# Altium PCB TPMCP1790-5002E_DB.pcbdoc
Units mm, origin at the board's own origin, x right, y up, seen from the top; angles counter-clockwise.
Board outline 20.84 x 19.35 mm, 2 copper layers (Top Layer, Bottom Layer), stack 0 mm thick; 1 components, 0 nets, 4 pads, 0 vias.
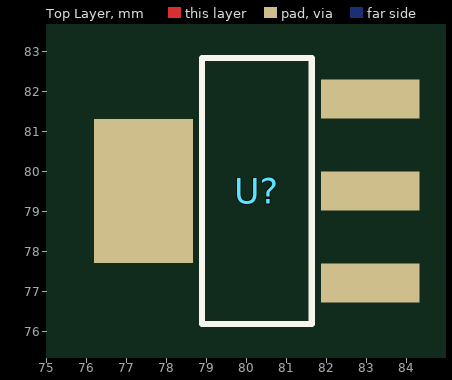
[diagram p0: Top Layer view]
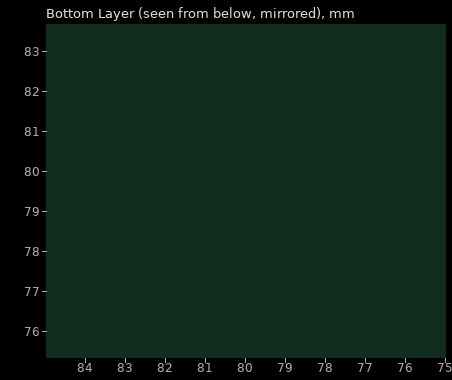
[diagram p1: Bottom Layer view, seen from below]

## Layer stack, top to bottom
Top Layer: signal copper (thickness not stored)
Bottom Layer: signal copper (thickness not stored)

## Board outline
90.69,69.85 69.85,69.85 69.85,89.202 90.69,89.202

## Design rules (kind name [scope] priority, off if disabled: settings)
PasteMaskExpansion "Paste Mask Expansion" [All] p1: expansion=0
SolderMaskExpansion "Solder Mask Expansion" [IsVia] p1: expansion=-25.4 istentingtop=TRUE
SolderMaskExpansion "Solder Mask Expansion" [All] p2: expansion=0.051 istentingtop=FALSE

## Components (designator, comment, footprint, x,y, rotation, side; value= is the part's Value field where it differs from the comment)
U? "TPMCP1790-5002E/DB" SOT-223-4_L6.5-W3.5-P2.30-LS7.0-BR 80.27,79.526 r0 top

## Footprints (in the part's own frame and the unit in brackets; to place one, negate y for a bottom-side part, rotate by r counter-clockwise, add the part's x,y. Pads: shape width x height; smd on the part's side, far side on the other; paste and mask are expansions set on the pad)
SOT-223-4_L6.5-W3.5-P2.30-LS7.0-BR [mm]
  rect 2.47x0.98 smd: 1(2.835,-2.3) 2(2.835,0) 3(2.835,2.3)
  rect 2.47x3.6 smd: 4(-2.835,0)
  silkscreen extent -1.37,-3.33 1.37,3.33

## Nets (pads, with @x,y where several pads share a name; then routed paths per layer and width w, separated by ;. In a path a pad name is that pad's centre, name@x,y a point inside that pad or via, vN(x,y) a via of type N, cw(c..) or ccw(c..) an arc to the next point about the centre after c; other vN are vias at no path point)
pads on no net: U?.1 U?.2 U?.3 U?.4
